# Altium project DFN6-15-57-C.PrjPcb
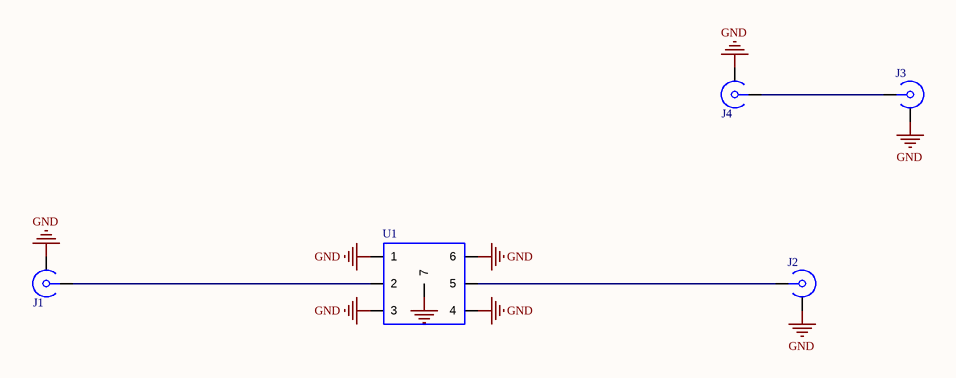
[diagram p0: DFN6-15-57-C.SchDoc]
Description: Layout updates; Modified From: DFN6-15-34-A (Eagle)
1 sheet, 5 parts. Net scope: global (net labels, ports and power ports of the same name join across sheets).
Board file: DFN6-15-57-C.PcbDoc

## Sheet DFN6-15-57-C.SchDoc
size 241 x 190 mm; Revision: A; SheetNumber: 1; SheetTotal: 1

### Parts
J1  Clamp_27G_Southwest_RevC  [Clamp_27G_Southwest_RevC]  (value not drawn)
J2  Clamp_27G_Southwest_RevC  [Clamp_27G_Southwest_RevC]  (value not drawn)
J3  Clamp_27G_Southwest_RevC  [Clamp_27G_Southwest_RevC]  (value not drawn)
J4  Clamp_27G_Southwest_RevC  [Clamp_27G_Southwest_RevC]  (value not drawn)
U1  DFN6_1.5x1.5mm_RevG  [DFN6_1.5x1.5mm_RevG]  (value not drawn)

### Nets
GND: J1.2 J2.2 J3.2 J4.2 U1.1 U1.3 U1.4 U1.6 U1.7
NetJ1_1: J1.1 U1.2
NetJ2_1: J2.1 U1.5
NetJ3_1: J3.1 J4.1

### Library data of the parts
J1-J4 = RF_Conn
U1 = DFN6_1.5x1.5mm: DFN6 1.5x1.5mm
